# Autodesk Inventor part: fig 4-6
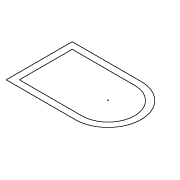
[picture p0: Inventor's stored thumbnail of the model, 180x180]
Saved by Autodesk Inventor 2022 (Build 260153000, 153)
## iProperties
Created: 2005-02
Part Number: fig 4-6
Document SubType Name: Modeling
Designer: CADCIM
Manufacturer: Standard
Standards Organization: Custom
Density: 1 g/cm^3
Material: Generic
Appearance: Default
Author: CADCIM
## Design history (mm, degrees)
sketch "Sketch1"
  geometry: L1 (12.963, 23.563)-(-25.99, 23.563); L2 (-25.99, 23.563)-(-25.99, -13.729); L3 (-25.99, -13.729)-(12.963, -13.729); L4 (-22.275, 19.848)-(12.963, 19.848); L5 (12.963, -10.014)-(-22.275, -10.014); L6 (-22.275, -10.014)-(-22.275, 19.848); A1 r 18.646 centre (12.963, 4.917) between (12.963, -13.729) and (12.963, 23.563); A2 r 14.931 centre (12.963, 4.917) between (12.963, -10.014) and (12.963, 19.848)
  constraints: 12 end point, 4 point on circle, 2 centre point, 2 parallel, 2 perpendicular, 2 tangent, 1 horizontal, 4 other
